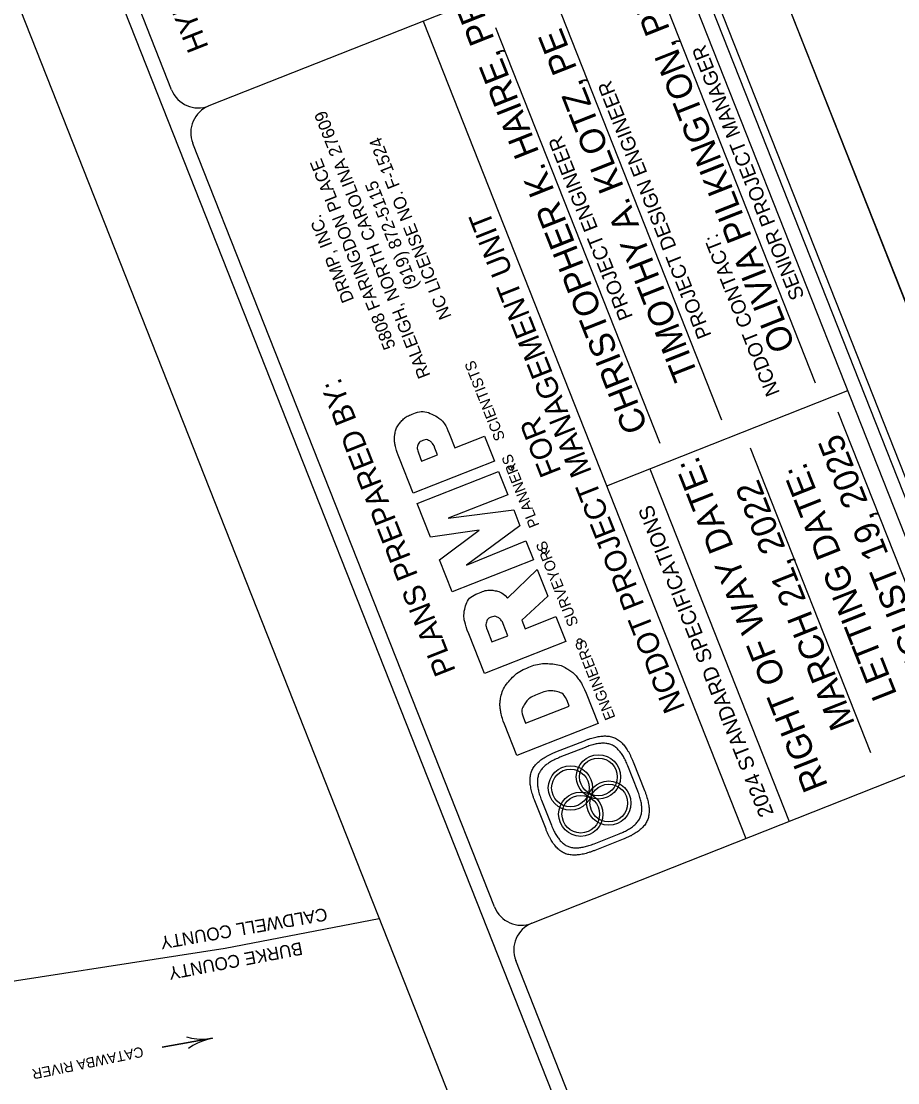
# Model space of a CAD drawing. Extents: x 1247235 to 1260080, y 742320 to 754020.
# Drawn here: x 1251398 to 1252768, y 748232 to 749890 of the extents above; entities that cross this region are included whole.
import ezdxf

# ---------------------------------------------------------------- set-up
doc = ezdxf.new("R2010")
doc.units = 0
for name, color, linetype in [('Default', 7, 'Continuous'), ('Exist Boundary County Line', 7, 'Continuous'), ('Exist Boundary County Line Text', 7, 'Continuous'), ('Exist Hydro River Flow Arrow CELL', 7, 'Continuous'), ('Exist Hydro Stream or Body of Water Text', 7, 'Continuous'), ('Pattern 1', 7, 'Continuous'), ('Pattern 2', 7, 'Continuous'), ('Scratch_Level_3', 7, 'Continuous'), ('Sheet Cutting Line CELL', 7, 'Continuous'), ('Sheet Data Field CELL', 7, 'Continuous'), ('Sheet Plot Border Inside CELL', 7, 'Continuous'), ('Sheet Plot Border Outside CELL', 7, 'Continuous'), ('Sheet Title CELL', 7, 'Continuous')]:
    doc.layers.add(name, color=color, linetype=linetype)

# ---------------------------------------------------------------- blocks, each defined once
blk = doc.blocks.new('EXIST HYDRO RIVER FLOW ARROW')
at = {"layer": 'Default'}
blk.add_line((0, 0), (0, 0), dxfattribs=at)
blk.add_lwpolyline([(0, 0.04575), (0.03775, 0.03), (0.07725, 0.01725), (0.118, 0.00775), (0.159, 0.0015), (0.2, 0), (-0.2, 0), (0.2, 0), (0.159, -0.0015), (0.118, -0.00775), (0.07725, -0.01725), (0.03775, -0.03), (0, -0.04575)], dxfattribs=at)

msp = doc.modelspace()

# ---------------------------------------------------------------- linework, layer by layer
at = {"layer": 'Exist Boundary County Line'}
msp.add_lwpolyline([(1251957.1, 748487.6), (1251716.2, 748441.3), (1251278.4, 748373.7)], dxfattribs=at)
at = {"layer": 'Pattern 1'}
for p, q in [((1252016.5, 749136.2), (1252143.5, 749186.4)), ((1252143.5, 749186.4), (1252158, 749149.8)), ((1252158, 749149.8), (1252064.6, 749113.6)), ((1252037.1, 749084), (1252016.5, 749136.2)), ((1252064.6, 749113.6), (1252167.3, 749126.2)), ((1252167.3, 749126.2), (1252177.1, 749101.6)), ((1252113.1, 749094.7), (1252037.1, 749084)), ((1252051.3, 749048.2), (1252113.1, 749094.7)), ((1252177.1, 749101.6), (1252093.7, 749040)), ((1252093.7, 749040), (1252186.3, 749078.2)), ((1252186.3, 749078.2), (1252198, 749048.5)), ((1252071, 748998.3), (1252051.3, 749048.2)), ((1252198, 749048.5), (1252071, 748998.3)), ((1252233.2, 748748.3), (1252277.8, 748765.9)), ((1252278.8, 748755.4), (1252239.6, 748740)), ((1252361.2, 748687.3), (1252345.7, 748726.5)), ((1252354, 748732.9), (1252371.7, 748688.3)), ((1252217.8, 748627.5), (1252200.2, 748672.1)), ((1252210.7, 748673.1), (1252226.2, 748633.9)), ((1252293, 748605), (1252332.2, 748620.4)), ((1252338.6, 748612.1), (1252294, 748594.5))]:
    msp.add_line(p, q, dxfattribs=at)
for points in [[(1252066.5, 749245.8), (1252075.4, 749223.3), (1252121.7, 749241.5), (1252137.1, 749202.6), (1252010.1, 749152.4), (1251988.7, 749206.5)], [(1252018.3, 749215.5), (1252023.4, 749202.7), (1252048.3, 749212.5), (1252044.2, 749223)], [(1252157.5, 748988.7), (1252204, 749033.5), (1252220.5, 748991.8), (1252179.8, 748953.9), (1252185, 748940.6), (1252233.2, 748959.6), (1252248.5, 748921), (1252121.5, 748870.8), (1252096.9, 748932.8)], [(1252126.2, 748938.1), (1252133.3, 748920.1), (1252158.1, 748929.9), (1252150.8, 748948.4)], [(1252280.5, 748840), (1252299.1, 748792.9), (1252172.1, 748742.6), (1252152.8, 748791.5)], [(1252182, 748803), (1252185.9, 748793.1), (1252254, 748820), (1252250.6, 748828.8)]]:
    msp.add_lwpolyline(points, dxfattribs=at)
for points, degree in [([(1251988.7, 749206.5), (1251985.3, 749215), (1251983.1, 749222.2), (1251981.9, 749228.2), (1251980.8, 749234.2), (1251980.6, 749239.5), (1251981.4, 749244.1), (1251982.8, 749251.5), (1251985.7, 749257.9), (1251990.3, 749263.2), (1251994.8, 749268.6), (1252000.7, 749272.7), (1252007.9, 749275.6), (1252020, 749280.3), (1252031.5, 749280), (1252042.2, 749274.5), (1252053, 749269.1), (1252061.1, 749259.5), (1252066.5, 749245.8)], 3), ([(1252044.2, 749223), (1252042.1, 749228.2), (1252039.4, 749231.9), (1252036, 749234), (1252032.7, 749236), (1252029, 749236.3), (1252025.1, 749234.7), (1252021.1, 749233.1), (1252018.5, 749230.7), (1252017.4, 749227.4), (1252016.2, 749224.1), (1252016.5, 749220.1), (1252018.3, 749215.5)], 3), ([(1252096.9, 748932.8), (1252090.4, 748949.4), (1252088.5, 748963.1), (1252091.4, 748973.8), (1252094.3, 748984.5), (1252102, 748992.3), (1252114.3, 748997.2), (1252122.9, 749000.6), (1252130.9, 749001.6), (1252138.3, 749000.2), (1252145.7, 748998.7), (1252152.1, 748994.9), (1252157.5, 748988.7)], 3), ([(1252150.8, 748948.4), (1252149, 748952.9), (1252146.4, 748956.2), (1252142.9, 748958.1), (1252139.5, 748960.1), (1252136, 748960.3), (1252132.3, 748958.9), (1252128.2, 748957.2), (1252125.6, 748954.7), (1252124.6, 748951.2), (1252123.6, 748947.7), (1252124.1, 748943.4), (1252126.2, 748938.1)], 3), ([(1252152.8, 748791.5), (1252149.8, 748799.2), (1252147.7, 748806.4), (1252146.7, 748813), (1252145.7, 748819.6), (1252145.7, 748825.7), (1252146.7, 748831.4), (1252148.8, 748842.3), (1252153.7, 748852), (1252161.4, 748860.6), (1252169.1, 748869.2), (1252179, 748875.9), (1252190.9, 748880.6), (1252201.5, 748884.8), (1252212.3, 748886.6), (1252223.2, 748886.1), (1252234.1, 748885.5), (1252243.8, 748882.6), (1252252.1, 748877.5), (1252258.3, 748873.7), (1252263.6, 748868.7), (1252268.2, 748862.6), (1252272.8, 748856.6), (1252276.9, 748849), (1252280.5, 748840)], 3), ([(1252250.6, 748828.8), (1252247.7, 748836.1), (1252242.3, 748840.7), (1252234.3, 748842.6), (1252226.3, 748844.5), (1252217.1, 748843.4), (1252206.6, 748839.3), (1252196.3, 748835.2), (1252188.9, 748829.9), (1252184.5, 748823.4), (1252180.1, 748816.8), (1252179.2, 748810), (1252182, 748803)], 3), ([(1252277.8, 748765.9), (1252307.8, 748777.8), (1252342.1, 748763), (1252354, 748732.9)], 2), ([(1252345.7, 748726.5), (1252335.3, 748752.8), (1252305.2, 748765.9), (1252278.8, 748755.4)], 2), ([(1252200.2, 748672.1), (1252188.3, 748702.1), (1252203.2, 748736.4), (1252233.2, 748748.3)], 2), ([(1252239.6, 748740), (1252213.3, 748729.5), (1252200.3, 748699.4), (1252210.7, 748673.1)], 2), ([(1252332.2, 748620.4), (1252358.5, 748630.9), (1252371.6, 748661), (1252361.2, 748687.3)], 2), ([(1252371.7, 748688.3), (1252383.5, 748658.3), (1252368.7, 748624), (1252338.6, 748612.1)], 2), ([(1252294, 748594.5), (1252264, 748582.6), (1252229.7, 748597.4), (1252217.8, 748627.5)], 2), ([(1252226.2, 748633.9), (1252236.6, 748607.6), (1252266.7, 748594.5), (1252293, 748605)], 2)]:
    msp.add_open_spline(points, degree=degree, dxfattribs=at)
at = {"layer": 'Pattern 2'}
for centre, radius in [((1252163.5, 749191.9), 3.67), ((1252214.5, 749062.9), 3.67), ((1252270.4, 748921.5), 3.67), ((1252299.7, 748709.3), 34.6), ((1252256, 748692), 34.6), ((1252299.7, 748709.3), 29.4), ((1252256, 748692), 29.4), ((1252315.9, 748668.4), 34.6), ((1252315.9, 748668.4), 29.4), ((1252272.1, 748651.1), 34.6), ((1252272.1, 748651.1), 29.4)]:
    msp.add_circle(centre, radius, dxfattribs=at)
at = {"layer": 'Scratch_Level_3'}
msp.add_lwpolyline([(1251095.3, 746040.1), (1249533.8, 749989.2), (1251115.9, 750614.8), (1252677.6, 746665.7)], close=True, dxfattribs=at)
at = {"layer": 'Sheet Cutting Line CELL'}
msp.add_line((1254624.4, 744786.1), (1251837.9, 751833.2), dxfattribs=at)
at = {"layer": 'Sheet Plot Border Inside CELL'}
msp.add_lwpolyline([(1254509, 744803.4), (1251751.5, 751777.2), (1247336.2, 750031.4), (1250093.7, 743057.5)], close=True, dxfattribs=at)
at = {"layer": 'Sheet Plot Border Outside CELL'}
msp.add_lwpolyline([(1247234.8, 750013.1), (1250021.3, 742966), (1254624.4, 744786.1), (1251837.9, 751833.2)], close=True, dxfattribs=at)
at = {"layer": 'Sheet Title CELL'}
for p, q in [((1253340.8, 745401.2), (1250991.2, 751343.5)), ((1251632.6, 749782.5), (1251302, 750618.5)), ((1252360.5, 750022), (1251691, 749757.2)), ((1252639, 749324.4), (1252380.5, 749978.3)), ((1252492.5, 749266.5), (1252234, 749920.4)), ((1252025.7, 749889.6), (1252530.3, 748613.2)), ((1252396, 749230), (1252139.3, 749879.3)), ((1252137.3, 748506.2), (1251665.7, 749698.8)), ((1252312.6, 749163.7), (1252689.4, 749312.7)), ((1252674, 749279.5), (1252862.2, 748803.5)), ((1252536.9, 749223.3), (1252725.1, 748747.3)), ((1252380.1, 749190.4), (1252597.7, 748639.8)), ((1252195.7, 748480.9), (1252865.2, 748745.6)), ((1252799.2, 746832.3), (1252170.4, 748422.5))]:
    msp.add_line(p, q, dxfattribs=at)
for points in [[(1254227, 745485.4), (1251778, 751678.9)], [(1252890.5, 748804), (1252419, 749996.7)]]:
    msp.add_lwpolyline(points, dxfattribs=at)
for centre, start, end in [((1251674.4, 749799.1), 201.5743, 291.5743), ((1251707.5, 749715.4), 111.5743, 201.5743), ((1252179.1, 748522.7), 201.5743, 291.5743), ((1252212.3, 748439), 111.5743, 201.5743)]:
    msp.add_arc(centre, 45, start, end, dxfattribs=at)

# ---------------------------------------------------------------- block references
at = {"layer": 'Exist Hydro River Flow Arrow CELL', "xscale": 200.00000000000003, "yscale": 200, "rotation": 9.926265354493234}
msp.add_blockref('EXIST HYDRO RIVER FLOW ARROW', (1251657.3, 748294.2), dxfattribs=at)

# ---------------------------------------------------------------- texts
at = {"layer": 'Exist Boundary County Line Text'}
for s, rotation, p in [('CALDWELL COUNTY', 189.8833, (1251874.1, 748505)), ('BURKE COUNTY', 190.7721, (1251835.1, 748451.6))]:
    msp.add_text(s, height=20, rotation=rotation, dxfattribs=at).set_placement(p)
at = {"layer": 'Exist Hydro Stream or Body of Water Text'}
msp.add_text('CATAWBA RIVER', height=16, rotation=191.6597, dxfattribs=at).set_placement((1251586.7, 748288.2))
at = {"layer": 'Pattern 2'}
for s, height, p in [('RALEIGH, NORTH CAROLINA 27609', 19.701, (1252037.3, 749336.3)), ('NC LICENSE NO. F-1524', 19.701, (1252070.4, 749428.4)), ('5808 FARINGDON PLACE', 19.701, (1251983.3, 749381.4)), ('(919) 872-5115', 19.701, (1252018.8, 749474.8)), ('DRMP, INC.', 19.7, (1251918.2, 749454.6)), ('ENGINEERS    SURVEYORS    PLANNERS    SCIENTISTS', 16.78, (1252326.6, 748802.2))]:
    msp.add_text(s, height=height, rotation=111.5743, dxfattribs=at).set_placement(p)
at = {"layer": 'Sheet Data Field CELL'}
for s, p in [('OLIVIA PILKINGTON, PE', (1252607.8, 749381.7)), ('CHRISTOPHER K. HAIRE, PE', (1252377.6, 749254.9)), ('TIMOTHY A. KLOTZ, PE', (1252456.1, 749337)), ('AUGUST 19, 2025', (1252839.7, 748839.6)), ('MARCH 21, 2022', (1252701.1, 748792.4))]:
    msp.add_text(s, height=39.375, rotation=111.5743, dxfattribs=at).set_placement(p)
at = {"layer": 'Sheet Title CELL'}
for s, height, p in [(' HYDRAULICS ', 33.75, (1251695.5, 749837.5)), ('SENIOR PROJECT MANAGER', 22.498, (1252622.1, 749459.6)), ('PROJECT DESIGN ENGINEER', 22.498, (1252476.7, 749399.1)), ('PROJECT ENGINEER', 22.498, (1252354, 749428)), ('NCDOT PROJECT MANAGEMENT UNIT', 33.75, (1252435.5, 748817.4)), ('NCDOT CONTACT:', 22.498, (1252583.7, 749309.2)), ('PLANS PREPARED BY:', 33.75, (1252077.1, 748875.1)), ('FOR', 33.75, (1252242.1, 749186.1)), ('RIGHT OF WAY DATE: ', 39.374, (1252658.9, 748695.7)), ('LETTING DATE:', 39.374, (1252766.9, 748838.4)), ('2024 STANDARD SPECIFICATIONS', 23.4, (1252574.2, 748652.3))]:
    msp.add_text(s, height=height, rotation=111.5743, dxfattribs=at).set_placement(p)

doc.saveas('drawing.dxf')
